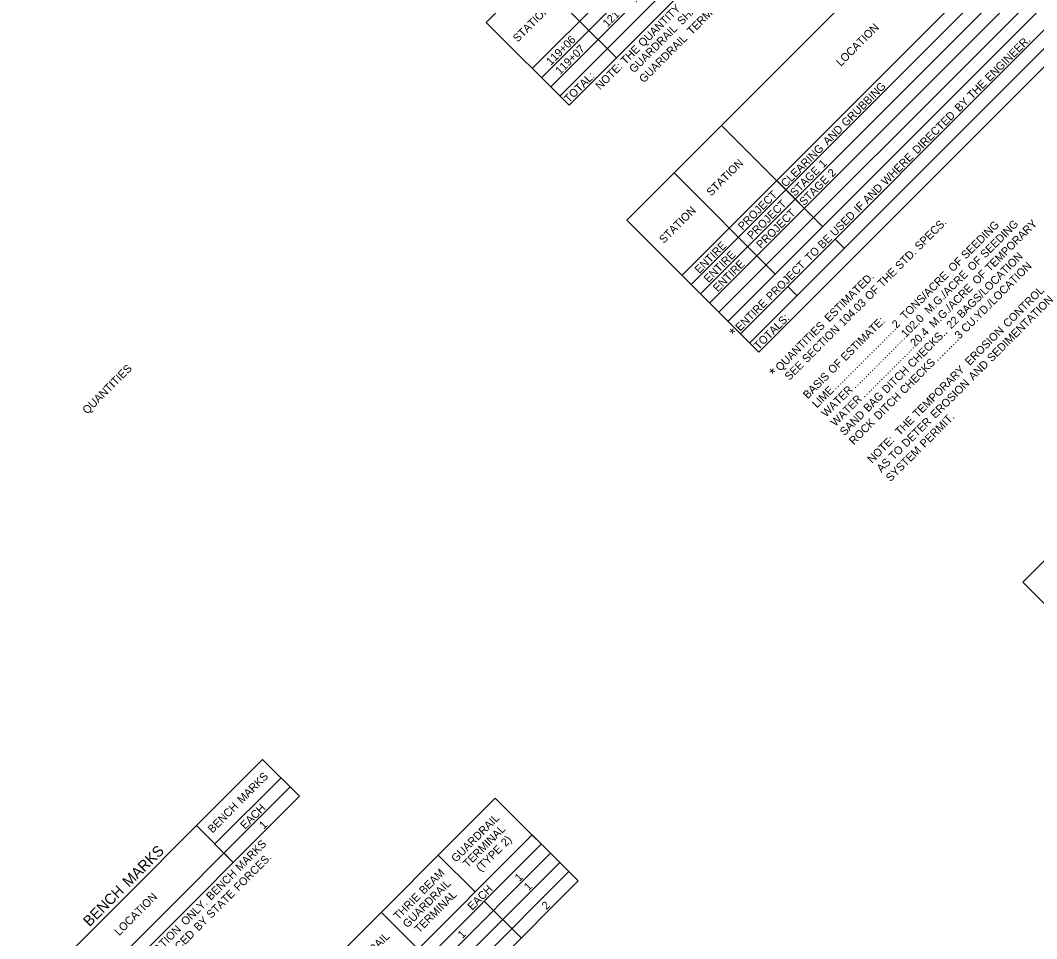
# Model space of a CAD drawing. Extents: x 1675667 to 1681231, y 227227 to 232694.
# Drawn here: x 1676602 to 1677364, y 228402 to 229090 of the extents above; entities that cross this region are included whole.
import ezdxf

# ---------------------------------------------------------------- set-up
doc = ezdxf.new("R2010")
doc.units = 0
doc.layers.add('Default', color=7, linetype='Continuous')
doc.layers.add('R_Border', color=7, linetype='Continuous')

msp = doc.modelspace()

# ---------------------------------------------------------------- linework, layer by layer
at = {"layer": 'Default'}
for p, q in [((1677056.44, 228939.89), (1677885.72, 229769.38)), ((1677097.81, 228898.53), (1677927.09, 229728.02)), ((1677104.71, 228891.64), (1677933.99, 229721.12)), ((1677111.6, 228884.75), (1677940.88, 229714.23)), ((1677118.5, 228877.85), (1677947.78, 229707.34)), ((1677125.39, 228870.96), (1677954.67, 229700.44)), ((1677132.29, 228864.07), (1677961.57, 229693.55)), ((1677141.59, 228854.76), (1677970.88, 229684.24)), ((1677148.49, 228847.87), (1677977.77, 229677.35)), ((1677155.38, 228840.97), (1677984.67, 229670.46)), ((1676951.15, 229088.05), (1677177.6, 229314.56)), ((1676985.63, 229053.58), (1677212.08, 229280.09)), ((1676985.63, 229053.58), (1677212.08, 229280.09)), ((1676992.52, 229046.69), (1677218.97, 229273.2)), ((1676999.42, 229039.8), (1677225.87, 229266.3)), ((1677006.31, 229032.9), (1677232.76, 229259.41)), ((1677013.21, 229026.01), (1677239.66, 229252.52)), ((1677021.13, 229089.09), (1676986.65, 229123.56)), ((1677013.21, 229026.01), (1676951.15, 229088.05)), ((1677013.21, 229026.01), (1676951.15, 229088.05)), ((1677048.71, 229061.52), (1677021.13, 229089.09)), ((1677203.29, 228935.09), (1677127.44, 229010.91)), ((1677353.22, 228668.55), (1677680.66, 228996.07)), ((1677167.79, 228899.58), (1677091.94, 228975.4)), ((1677203.29, 228935.09), (1677168.81, 228969.55)), ((1677042.65, 228945.41), (1677042.65, 228945.41)), ((1677155.38, 228840.97), (1677056.44, 228939.89)), ((1677155.38, 228840.97), (1677056.44, 228939.89)), ((1677167.79, 228899.58), (1677133.31, 228934.04)), ((1677219.49, 228918.89), (1677212.6, 228925.78)), ((1677219.49, 228918.89), (1677212.6, 228925.78)), ((1677183.99, 228883.38), (1677177.1, 228890.27)), ((1677183.99, 228883.38), (1677177.1, 228890.27)), ((1677339.43, 228674.06), (1677339.43, 228674.06)), ((1677435.96, 228585.83), (1677353.22, 228668.55)), ((1677435.96, 228585.83), (1677353.22, 228668.55)), ((1676588.43, 228340.79), (1676783.51, 228535.92)), ((1676811.09, 228508.35), (1676783.51, 228535.92)), ((1676747.67, 228472.49), (1676797.3, 228522.14)), ((1676811.09, 228508.35), (1676797.3, 228522.14)), ((1676609.11, 228320.11), (1676804.2, 228515.24)), ((1676616.01, 228313.22), (1676811.09, 228508.35)), ((1676649.1, 228198.02), (1676957.92, 228506.92)), ((1677019.98, 228444.88), (1676957.92, 228506.92)), ((1676761.46, 228458.7), (1676733.88, 228486.28)), ((1676857.29, 228351.1), (1676985.5, 228479.35)), ((1677019.98, 228444.88), (1676985.5, 228479.35)), ((1676683.57, 228163.56), (1676992.4, 228472.46)), ((1676690.47, 228156.66), (1676999.3, 228465.56)), ((1676697.36, 228149.77), (1677006.19, 228458.67)), ((1676761.46, 228458.7), (1676754.57, 228465.6)), ((1676942.77, 228436.6), (1676915.18, 228464.17)), ((1676704.26, 228142.87), (1677013.09, 228451.78)), ((1676711.15, 228135.98), (1677019.98, 228444.88)), ((1676977.24, 228402.13), (1676949.66, 228429.71)), ((1676977.24, 228402.13), (1676949.66, 228429.71)), ((1676934.5, 228359.38), (1676872.45, 228421.42))]:
    msp.add_line(p, q, dxfattribs=at)

# ---------------------------------------------------------------- texts
for s, height, p in [(' TERMINALS', 6, (1677103.61, 229076.76)), ('121+08', 6, (1677041.99, 229084.07)), ('STATION', 6, (1676974.67, 229072.86)), (' QUANTITY', 6, (1677066.99, 229067.71)), (' SHALL', 6, (1677096.24, 229084.13)), ('GUARDRAIL', 6, (1677061.86, 229049.75)), ('LOCATION', 6, (1677216.87, 229054.75)), ('119+06', 6, (1676999.59, 229055.46)), ('GUARDRAIL', 6, (1677069.24, 229042.38)), (' ENGINEER.', 6, (1677326.9, 229041.81)), ('119+07', 6, (1677006.49, 229048.57)), ('THE', 6, (1677055.45, 229056.16)), ('NOTE:', 6, (1677036.47, 229037.19)), ('TOTAL:', 6, (1677013.05, 229027.55)), (' THE', 6, (1677313.72, 229028.62)), (' GRUBBING', 6, (1677219.32, 229007.98)), (' BY', 6, (1677304.21, 229019.11)), (' DIRECTED', 6, (1677272.58, 228987.47)), (' AND', 6, (1677205.48, 228994.13)), ('CLEARING', 6, (1677175.55, 228964.2)), ('STATION', 6, (1677119.73, 228957.58)), (' 1', 6, (1677202.22, 228977.09)), (' WHERE', 6, (1677249.19, 228964.07)), ('STAGE', 6, (1677182.44, 228957.3)), (' 2', 6, (1677209.12, 228970.19)), ('STAGE', 6, (1677189.34, 228950.41)), ('PROJECT', 6, (1677143.33, 228931.97)), (' AND', 6, (1677235.34, 228950.23)), ('PROJECT', 6, (1677150.23, 228925.08)), (' IF', 6, (1677228.7, 228943.58)), ('STATION', 6, (1677084.23, 228922.07)), ('PROJECT', 6, (1677157.13, 228918.19)), (' USED', 6, (1677210.9, 228925.78)), (' SPECS.', 6, (1677274.3, 228915.42)), (' SEEDING', 6, (1677309.05, 228908.8)), (' SEEDING', 6, (1677323.45, 228909.42)), (' TEMPORARY', 6, (1677327.05, 228899.23)), ('ENTIRE', 6, (1677110.9, 228899.53)), (' BE', 6, (1677201.66, 228916.54)), ('ENTIRE', 6, (1677117.79, 228892.64)), (' TO', 6, (1677192.05, 228906.92)), (' STD.', 6, (1677259.67, 228900.78)), (' BAGS/LOCATION', 6, (1677305.97, 228864.35)), ('ENTIRE', 6, (1677124.69, 228885.74)), (' PROJECT', 6, (1677162.86, 228877.72)), (' OF', 6, (1677299.44, 228899.19)), (' CU.YD./LOCATION', 6, (1677309.1, 228853.69)), (' OF', 6, (1677313.85, 228899.81)), (' THE', 6, (1677246.48, 228887.59)), (' TONS/ACRE', 6, (1677263.53, 228863.27)), (' M.G./ACRE', 6, (1677281.56, 228867.52)), (' OF', 6, (1677317.44, 228889.62)), (' ESTIMATED.', 6, (1677206.69, 228861.58)), (' OF', 6, (1677236.88, 228877.98)), (' M.G./ACRE', 6, (1677285.16, 228857.33)), (' CONTROL', 6, (1677340.46, 228857.48)), ('ENTIRE', 6, (1677141.44, 228856.3)), (' 104.03', 6, (1677217.38, 228858.48)), (' SEDIMENTATION', 6, (1677328.49, 228831.71)), ('TOTALS:', 6, (1677155.23, 228842.51)), ('QUANTITIES', 6, (1677171.43, 228826.31)), (' ESTIMATE:', 6, (1677218.87, 228832.4)), ('..........................2', 6, (1677217.76, 228817.49)), ('.....................102.0', 6, (1677232.46, 228818.41)), (' 22', 6, (1677298.05, 228856.43)), ('*', 8, (1677138.13, 228851.29)), (' SECTION', 6, (1677189.87, 228830.97)), ('.....................20.4', 6, (1677239.36, 228811.51)), (' CHECKS..', 6, (1677268.92, 228827.29)), ('....3', 6, (1677299.49, 228844.08)), (' EROSION', 6, (1677311.96, 228828.97)), ('…', 6, (1677294.25, 228838.84)), ('SEE', 6, (1677178.32, 228819.42)), (' OF', 6, (1677209.27, 228822.79)), (' CHECKS', 6, (1677262.98, 228807.56)), ('…', 6, (1677289.02, 228833.61)), (' AND', 6, (1677314.64, 228817.87)), ('*', 8, (1677168.12, 228821.3)), ('BASIS', 6, (1677192.11, 228805.63)), (' DITCH', 6, (1677249.64, 228808.01)), (' TEMPORARY', 6, (1677272.81, 228789.81)), ('…', 6, (1677212.53, 228812.26)), ('…', 6, (1677227.23, 228813.17)), (' EROSION', 6, (1677286.14, 228789.36)), ('LIME', 6, (1677199.01, 228798.74)), ('WATER', 6, (1677205.9, 228791.84)), (' BAG', 6, (1677235.85, 228794.21)), ('…', 6, (1677234.12, 228806.28)), (' DITCH', 6, (1677243.7, 228788.28)), ('WATER', 6, (1677212.8, 228784.95)), ('SAND', 6, (1677219.7, 228778.06)), (' PERMIT.', 6, (1677278.1, 228767.52)), ('ROCK', 6, (1677226.59, 228771.16)), ('  THE', 6, (1677257.98, 228774.98)), (' DETER', 6, (1677264.49, 228767.7)), ('NOTE:', 6, (1677240.38, 228757.38)), ('SYSTEM', 6, (1677254.17, 228743.59)), (' TO', 6, (1677254.87, 228758.08)), ('AS', 6, (1677247.28, 228750.48)), (' MARKS', 6, (1676766.48, 228500.85)), ('BENCH', 6, (1676745.86, 228480.22)), ('EACH', 6, (1676770.36, 228483.1)), ('1', 6, (1676784.33, 228483.27)), ('GUARDRAIL', 6, (1676928.41, 228458.31)), ('TERMINAL', 6, (1676937.24, 228454.42)), (' MARKS', 6, (1676765.08, 228450.23)), (' 2)', 6, (1676964.11, 228468.56)), (' MARKS', 8, (1676681.23, 228437.61)), ('(TYPE', 6, (1676946.95, 228451.39)), (' FORCES.', 6, (1676763.84, 228435.2)), (' BENCH', 6, (1676743.16, 228428.3)), (' BEAM', 6, (1676902.77, 228432.66)), ('GUARDRAIL', 6, (1676892.03, 228409.19)), ('1', 6, (1676975.97, 228443.93)), ('1', 6, (1676982.87, 228437.04)), ('BENCH', 8, (1676653.74, 228410.11)), ('LOCATION', 6, (1676675.96, 228403.41)), (' STATE', 6, (1676743.41, 228414.76)), ('THRIE', 6, (1676885.28, 228415.17)), ('TERMINAL', 6, (1676900.87, 228405.3)), ('EACH', 6, (1676940.64, 228422.38)), (' ONLY.', 6, (1676724.24, 228409.38)), ('2', 6, (1676996.26, 228422.86)), (' BY', 6, (1676733.9, 228405.25)), (' INFORMATION', 6, (1676681.59, 228366.72)), (' PLACED', 6, (1676708.85, 228380.19)), ('1', 6, (1676933.23, 228401.18)), ('GUARDRAIL', 6, (1676846.11, 228369.63))]:
    msp.add_text(s, height=height, rotation=45.00703, dxfattribs=at).set_placement(p)
at = {"layer": 'R_Border'}
msp.add_text('QUANTITIES', height=6, rotation=45.00703, dxfattribs=at).set_placement((1676652.02, 228794.16))

doc.saveas('drawing.dxf')
